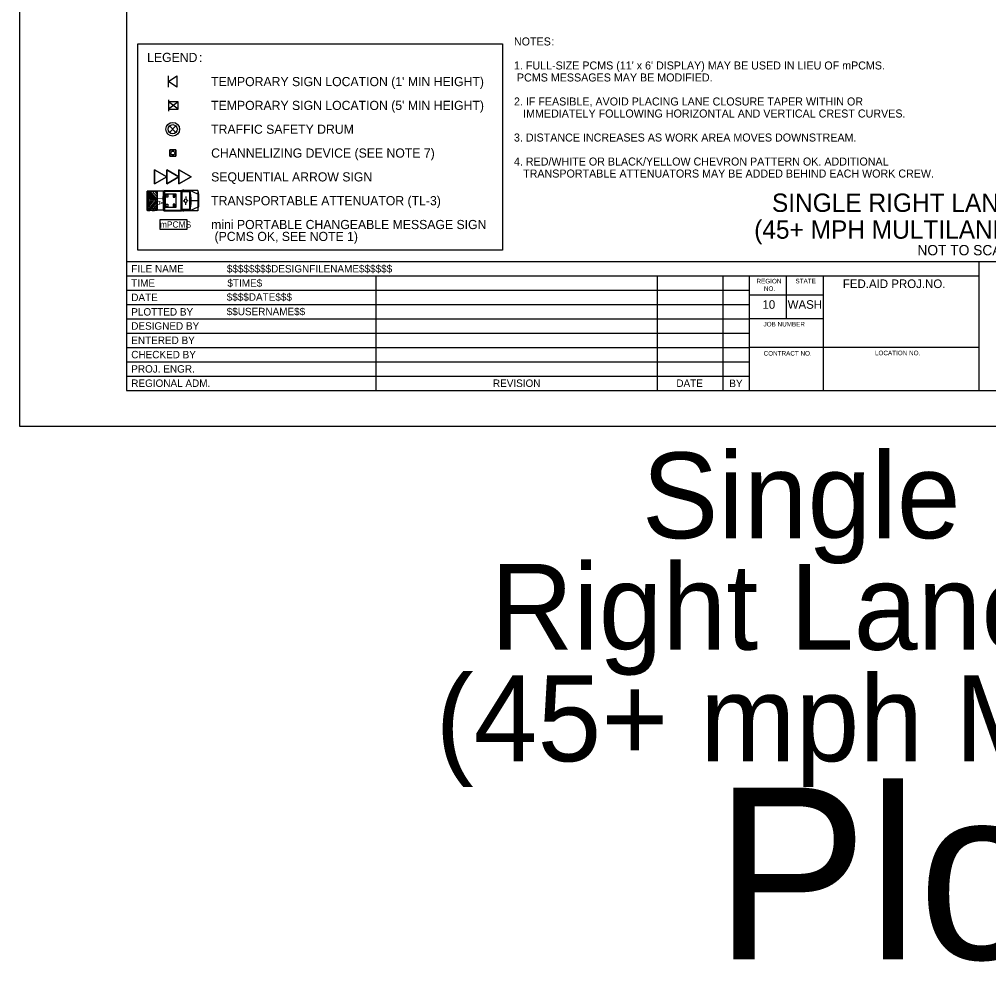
# Model space of a CAD drawing. Extents: x 99958 to 100176, y 99935 to 100011.
# Drawn here: x 99999.06 to 100007.54, y 99995.01 to 100003.24 of the extents above; entities that cross this region are included whole.
import ezdxf

# ---------------------------------------------------------------- set-up
doc = ezdxf.new("R2010")
doc.units = 0
for name, color, linetype in [('SH_DE_DetailHeading1Text', 7, 'Continuous'), ('SH_GI_GeneralNotesBodyText', 7, 'Continuous'), ('SH_GI_PlotLimits', 7, 'Continuous'), ('SH_GI_SheetBorder', 7, 'Continuous'), ('SH_GI_SheetLocationText', 7, 'Continuous'), ('SH_GI_SheetTextInCells', 7, 'Continuous'), ('SH_GI_TitleBlockText', 7, 'Continuous'), ('TR_WZ_PCMS', 7, 'Continuous'), ('TR_WZ_PortableSignMount5ftMinBlk-Wht', 7, 'Continuous'), ('TR_WZ_PortableSignMountBlk-Wht', 7, 'Continuous'), ('TR_WZ_SequentialArrowSign', 7, 'Continuous'), ('TR_WZ_TrafficCone', 7, 'Continuous'), ('TR_WZ_TrafficSafetyDrum', 7, 'Continuous'), ('TR_WZ_TransportableAttenuator', 7, 'Continuous'), ('TR_WZ_WorkZoneTextCurrent', 7, 'Continuous')]:
    doc.layers.add(name, color=color, linetype=linetype)

msp = doc.modelspace()

# ---------------------------------------------------------------- linework, layer by layer
at = {"layer": 'SH_GI_PlotLimits'}
msp.add_lwpolyline([(99999.0625, 99999.6875), (100016.0625, 99999.6875), (100016.0625, 100010.6875), (99999.0625, 100010.6875)], close=True, dxfattribs=at)
at = {"layer": 'SH_GI_SheetBorder'}
for p, q in [((100000, 100010.375), (100000, 100000)), ((100000, 100001.1259), (100015.75, 100001.1259)), ((100007.4566, 100000), (100007.4566, 100001.1259)), ((100000, 100001.0008), (100007.4566, 100001.0008)), ((100002.179, 100001.0008), (100002.179, 100000)), ((100004.641, 100001.0008), (100004.641, 100000)), ((100005.2164, 100001.0008), (100005.2164, 100000)), ((100005.4451, 100001.0008), (100005.4451, 100000)), ((100005.7719, 100000.6255), (100005.7719, 100001.0008)), ((100006.0956, 100000), (100006.0956, 100001.0008)), ((100000, 100000.8757), (100002.1821, 100000.8757)), ((100002.1821, 100000.8757), (100005.4466, 100000.8757)), ((100006.0958, 100000.831), (100005.4466, 100000.831)), ((100000, 100000.7506), (100002.1821, 100000.7506)), ((100002.1821, 100000.7506), (100005.4466, 100000.7506)), ((100000, 100000.6255), (100005.4466, 100000.6255)), ((100006.0958, 100000.6255), (100005.4466, 100000.6255)), ((100000, 100000.5004), (100005.4466, 100000.5004)), ((100000, 100000.3753), (100005.4466, 100000.3753)), ((100007.4566, 100000.3753), (100005.4466, 100000.3753)), ((100000, 100000.2502), (100005.4466, 100000.2502)), ((100000, 100000.1251), (100005.4466, 100000.1251)), ((100000, 100000), (100015.75, 100000))]:
    msp.add_line(p, q, dxfattribs=at)
at = {"layer": 'TR_WZ_PCMS'}
msp.add_lwpolyline([(100000.2899, 100001.41), (100000.5299, 100001.41), (100000.5299, 100001.49), (100000.2899, 100001.49)], close=True, dxfattribs=at)
msp.add_lwpolyline([(100000.2899, 100001.41), (100000.5299, 100001.41), (100000.5299, 100001.49), (100000.2899, 100001.49), (100000.2899, 100001.41)], dxfattribs=at)
at = {"layer": 'TR_WZ_PortableSignMount5ftMinBlk-Wht'}
for p, q in [((100000.3682, 100002.5414), (100000.3682, 100002.4414)), ((100000.4516, 100002.4589), (100000.3682, 100002.5239)), ((100000.4516, 100002.5239), (100000.3682, 100002.4589)), ((100000.4099, 100002.4914), (100000.4099, 100002.4914)), ((100000.41, 100002.4914), (100000.41, 100002.4914))]:
    msp.add_line(p, q, dxfattribs=at)
msp.add_lwpolyline([(100000.4516, 100002.4589), (100000.4516, 100002.5239), (100000.3682, 100002.5239), (100000.3682, 100002.4589)], close=True, dxfattribs=at)
at = {"layer": 'TR_WZ_PortableSignMountBlk-Wht'}
msp.add_line((100000.3682, 100002.6497), (100000.3682, 100002.7497), dxfattribs=at)
msp.add_lwpolyline([(100000.3682, 100002.6996), (100000.44, 100002.7497), (100000.44, 100002.6497)], close=True, dxfattribs=at)
at = {"layer": 'TR_WZ_SequentialArrowSign'}
for points in [[(100000.3508, 100001.8666), (100000.2441, 100001.8048), (100000.2441, 100001.9284), (100000.3508, 100001.8666)], [(100000.2441, 100001.9284), (100000.2441, 100001.8048), (100000.3508, 100001.8666), (100000.2441, 100001.9284)], [(100000.4575, 100001.8666), (100000.3508, 100001.8048), (100000.3508, 100001.8666), (100000.3508, 100001.9284), (100000.4575, 100001.8666)], [(100000.3508, 100001.9284), (100000.3508, 100001.8666), (100000.3508, 100001.8048), (100000.4575, 100001.8666), (100000.3508, 100001.9284)], [(100000.5641, 100001.8666), (100000.4575, 100001.8048), (100000.4575, 100001.8666), (100000.4575, 100001.9284), (100000.5641, 100001.8666)], [(100000.4575, 100001.9284), (100000.4575, 100001.8666), (100000.4575, 100001.8048), (100000.5641, 100001.8666), (100000.4575, 100001.9284)]]:
    msp.add_lwpolyline(points, dxfattribs=at)
at = {"layer": 'TR_WZ_TrafficCone'}
for points in [[(100000.4308, 100002.1016), (100000.4308, 100002.0482), (100000.3775, 100002.0482), (100000.3775, 100002.1016), (100000.4308, 100002.1016)], [(100000.3775, 100002.1016), (100000.3775, 100002.0482), (100000.4308, 100002.0482), (100000.4308, 100002.1016), (100000.3775, 100002.1016)]]:
    msp.add_lwpolyline(points, dxfattribs=at)
msp.add_circle((100000.4041, 100002.0749), 0.0167, dxfattribs=at)
at = {"layer": 'TR_WZ_TrafficSafetyDrum'}
for p, q in [((100000.4324, 100002.3114), (100000.3758, 100002.2549)), ((100000.4324, 100002.2549), (100000.3758, 100002.3114))]:
    msp.add_line(p, q, dxfattribs=at)
for radius in [0.06, 0.06, 0.04]:
    msp.add_circle((100000.4041, 100002.2832), radius, dxfattribs=at)
at = {"layer": 'TR_WZ_TransportableAttenuator'}
for p, q in [((100000.1791, 100001.7269), (100000.2355, 100001.659)), ((100000.1791, 100001.705), (100000.1791, 100001.7269)), ((100000.2355, 100001.659), (100000.1791, 100001.7269)), ((100000.1791, 100001.7269), (100000.1791, 100001.705)), ((100000.2174, 100001.6592), (100000.1791, 100001.705)), ((100000.1791, 100001.705), (100000.2174, 100001.6592)), ((100000.2551, 100001.6585), (100000.185, 100001.743)), ((100000.185, 100001.743), (100000.2041, 100001.743)), ((100000.185, 100001.743), (100000.2551, 100001.6585)), ((100000.2041, 100001.743), (100000.185, 100001.743)), ((100000.2041, 100001.743), (100000.2676, 100001.6659)), ((100000.2676, 100001.6659), (100000.2041, 100001.743)), ((100000.2676, 100001.6908), (100000.2248, 100001.743)), ((100000.2248, 100001.743), (100000.2439, 100001.743)), ((100000.2439, 100001.743), (100000.2248, 100001.743)), ((100000.2248, 100001.743), (100000.2676, 100001.6908)), ((100000.2439, 100001.743), (100000.2676, 100001.7144)), ((100000.2676, 100001.7144), (100000.2439, 100001.743)), ((100000.2676, 100001.574), (100000.2676, 100001.743)), ((100000.3279, 100001.743), (100000.2676, 100001.743)), ((100000.2676, 100001.7144), (100000.2676, 100001.6908)), ((100000.2676, 100001.6908), (100000.2676, 100001.7144)), ((100000.3208, 100001.7399), (100000.3208, 100001.5768)), ((100000.3241, 100001.7454), (100000.3274, 100001.7454)), ((100000.3274, 100001.7454), (100000.3274, 100001.5713)), ((100000.3279, 100001.7483), (100000.4803, 100001.7483)), ((100000.3279, 100001.7483), (100000.3279, 100001.5683)), ((100000.3279, 100001.7427), (100000.3279, 100001.574)), ((100000.3323, 100001.7411), (100000.3323, 100001.5755)), ((100000.3323, 100001.7411), (100000.476, 100001.7411)), ((100000.476, 100001.7411), (100000.476, 100001.5755)), ((100000.4803, 100001.7483), (100000.4803, 100001.5683)), ((100000.4824, 100001.7483), (100000.4824, 100001.5683)), ((100000.6223, 100001.7483), (100000.4824, 100001.7483)), ((100000.551, 100001.7344), (100000.4824, 100001.7344)), ((100000.5014, 100001.7509), (100000.493, 100001.7509)), ((100000.5175, 100001.694), (100000.5175, 100001.6794)), ((100000.551, 100001.7483), (100000.5421, 100001.7344)), ((100000.551, 100001.7483), (100000.551, 100001.5683)), ((100000.5523, 100001.7483), (100000.5523, 100001.5683)), ((100000.6223, 100001.7153), (100000.5523, 100001.7483)), ((100000.6223, 100001.7483), (100000.6223, 100001.5683)), ((100000.6223, 100001.7483), (100000.6291, 100001.712)), ((100000.6291, 100001.712), (100000.6291, 100001.6047)), ((100000.1791, 100001.6818), (100000.1987, 100001.6586)), ((100000.1791, 100001.635), (100000.1791, 100001.6818)), ((100000.1987, 100001.6586), (100000.1791, 100001.6818)), ((100000.1791, 100001.6818), (100000.1791, 100001.635)), ((100000.1791, 100001.6131), (100000.2174, 100001.6592)), ((100000.2174, 100001.6592), (100000.1791, 100001.6131)), ((100000.2355, 100001.659), (100000.1791, 100001.5911)), ((100000.1791, 100001.5911), (100000.2355, 100001.659)), ((100000.1987, 100001.6586), (100000.1791, 100001.635)), ((100000.1791, 100001.635), (100000.1987, 100001.6586)), ((100000.1791, 100001.5911), (100000.1791, 100001.6131)), ((100000.1791, 100001.6131), (100000.1791, 100001.5911)), ((100000.1849, 100001.5739), (100000.2551, 100001.6585)), ((100000.2551, 100001.6585), (100000.1849, 100001.5739)), ((100000.2676, 100001.6509), (100000.2037, 100001.5739)), ((100000.2037, 100001.5739), (100000.2676, 100001.6509)), ((100000.2243, 100001.5739), (100000.2676, 100001.626)), ((100000.2676, 100001.626), (100000.2243, 100001.5739)), ((100000.2676, 100001.6659), (100000.2676, 100001.6509)), ((100000.2676, 100001.6509), (100000.2676, 100001.6659)), ((100000.2676, 100001.626), (100000.2676, 100001.6011)), ((100000.2676, 100001.6011), (100000.2676, 100001.626)), ((100000.3208, 100001.671), (100000.3274, 100001.6676)), ((100000.3208, 100001.6456), (100000.3274, 100001.649)), ((100000.3226, 100001.6583), (100000.3257, 100001.6583)), ((100000.3241, 100001.6608), (100000.3241, 100001.6558)), ((100000.4951, 100001.6584), (100000.5045, 100001.6584)), ((100000.507, 100001.658), (100000.507, 100001.658)), ((100000.5175, 100001.6226), (100000.5175, 100001.6372)), ((100000.5398, 100001.6584), (100000.5305, 100001.6584)), ((100000.6223, 100001.6583), (100000.566, 100001.6583)), ((100000.2037, 100001.5739), (100000.1849, 100001.5739)), ((100000.1849, 100001.5739), (100000.2037, 100001.5739)), ((100000.2446, 100001.5739), (100000.2243, 100001.5739)), ((100000.2243, 100001.5739), (100000.2446, 100001.5739)), ((100000.2676, 100001.6011), (100000.2446, 100001.5739)), ((100000.2446, 100001.5739), (100000.2676, 100001.6011)), ((100000.3279, 100001.574), (100000.2676, 100001.574)), ((100000.3241, 100001.5713), (100000.3274, 100001.5713)), ((100000.3279, 100001.5683), (100000.4803, 100001.5683)), ((100000.3323, 100001.5755), (100000.476, 100001.5755)), ((100000.551, 100001.5823), (100000.4824, 100001.5823)), ((100000.6223, 100001.5683), (100000.4824, 100001.5683)), ((100000.5014, 100001.5658), (100000.493, 100001.5658)), ((100000.5437, 100001.5823), (100000.551, 100001.5683)), ((100000.6223, 100001.6013), (100000.5523, 100001.5683)), ((100000.6223, 100001.5683), (100000.6291, 100001.6047))]:
    msp.add_line(p, q, dxfattribs=at)
for points in [[(100000.2676, 100001.5739), (100000.1791, 100001.5739), (100000.1791, 100001.743), (100000.2676, 100001.743)], [(100000.3398, 100001.7183), (100000.4298, 100001.7183), (100000.4298, 100001.5983), (100000.3398, 100001.5983)], [(100000.3473, 100001.7108), (100000.3623, 100001.7108), (100000.3623, 100001.6883), (100000.3473, 100001.6883)], [(100000.4223, 100001.7108), (100000.4073, 100001.7108), (100000.4073, 100001.6883), (100000.4223, 100001.6883)], [(100000.3473, 100001.6283), (100000.3623, 100001.6283), (100000.3623, 100001.6058), (100000.3473, 100001.6058)], [(100000.4223, 100001.6283), (100000.4073, 100001.6283), (100000.4073, 100001.6058), (100000.4223, 100001.6058)]]:
    msp.add_lwpolyline(points, close=True, dxfattribs=at)
msp.add_lwpolyline([(100000.2676, 100001.743), (100000.1791, 100001.743), (100000.1791, 100001.5739), (100000.2676, 100001.574)], dxfattribs=at)
for centre, major_axis, start_param, end_param in [((100000.3241, 100001.7399), (0, 0.00549), 6.283185, 7.853982), ((100000.4523, 100001.6583), (0, 0.1889), 4.215852, 5.209111), ((100000.3241, 100001.5768), (0, -0.00549), 4.712389, 6.283185)]:
    msp.add_ellipse(centre, major_axis=major_axis, ratio=0.60201, start_param=start_param, end_param=end_param, dxfattribs=at)
for centre, major_axis in [((100000.3241, 100001.6583), (0, -0.00254)), ((100000.5175, 100001.6583), (0, -0.0173))]:
    msp.add_ellipse(centre, major_axis=major_axis, ratio=0.60201, dxfattribs=at)
at = {"layer": 'TR_WZ_WorkZoneTextCurrent'}
msp.add_lwpolyline([(100000.1, 100003.031), (100003.2886, 100003.031), (100003.2886, 100001.2259), (100000.1, 100001.2259)], close=True, dxfattribs=at)

# ---------------------------------------------------------------- texts
at = {"layer": 'SH_DE_DetailHeading1Text'}
for s, height, p in [('SINGLE RIGHT LANE CLOSURE', 0.16, (100005.6453, 100001.5606)), ('(45+ MPH MULTILANE HIGHWAYS)', 0.16, (100005.4898, 100001.3259)), ('NOT TO SCALE', 0.09, (100006.9175, 100001.1809))]:
    msp.add_text(s, height=height, rotation=360, dxfattribs=at).set_placement(p)
at = {"layer": 'SH_GI_GeneralNotesBodyText'}
for s, p in [('NOTES', (100003.3886, 100003.0156)), (':', (100003.7161, 100003.0156)), ("1. FULL-SIZE PCMS (11' x 6' DISPLAY) MAY BE USED IN LIEU OF mPCMS.", (100003.3886, 100002.8056)), (' PCMS MESSAGES MAY BE MODIFIED.', (100003.3886, 100002.7006)), ('2. IF FEASIBLE, AVOID PLACING LANE CLOSURE TAPER WITHIN OR ', (100003.3886, 100002.4906)), ('IMMEDIATELY FOLLOWING HORIZONTAL AND VERTICAL CREST CURVES.', (100003.4686, 100002.3856)), ('3. DISTANCE INCREASES AS WORK AREA MOVES DOWNSTREAM.', (100003.3886, 100002.1756)), ('4. RED/WHITE OR BLACK/YELLOW CHEVRON PATTERN OK. ADDITIONAL ', (100003.3886, 100001.9656)), ('TRANSPORTABLE ATTENUATORS MAY BE ADDED BEHIND EACH WORK CREW.', (100003.4686, 100001.8606))]:
    msp.add_text(s, height=0.07, rotation=360, dxfattribs=at).set_placement(p)
at = {"layer": 'SH_GI_SheetLocationText'}
for s, height, p in [('Single PCMS', 0.75, (100004.5076, 99998.7071)), ('Right Lane Closure', 0.75, (100003.1834, 99997.7321)), ('(45+ mph ML Hwys)', 0.75, (100002.7028, 99996.7571)), ('Plot 1', 1.5, (100005.1422, 99995.0267))]:
    msp.add_text(s, height=height, dxfattribs=at).set_placement(p)
at = {"layer": 'SH_GI_SheetTextInCells'}
for s, height, p in [('FILE NAME', 0.06505, (100000.041, 100001.0308)), ('TIME', 0.06505, (100000.041, 100000.9057)), ('REGION', 0.04003, (100005.5099, 100000.9352)), ('STATE', 0.04003, (100005.8511, 100000.9357)), ('FED.AID PROJ.NO.', 0.07506, (100006.2652, 100000.8945)), ('DATE', 0.06505, (100000.041, 100000.7806)), ('NO.', 0.04003, (100005.5752, 100000.869)), ('10', 0.07506, (100005.5621, 100000.7131)), ('WASH', 0.07506, (100005.7826, 100000.7131)), ('PLOTTED BY', 0.06505, (100000.041, 100000.6538)), ('DESIGNED BY', 0.065052, (100000.041, 100000.5304)), ('JOB NUMBER', 0.04003, (100005.5712, 100000.5587)), ('ENTERED BY', 0.06505, (100000.041, 100000.4053)), ('CHECKED BY', 0.06505, (100000.041, 100000.2802)), ('CONTRACT NO.', 0.040032, (100005.5725, 100000.3037)), ('LOCATION NO.', 0.040032, (100006.5465, 100000.3067)), ('PROJ. ENGR.', 0.065052, (100000.041, 100000.1551)), ('REGIONAL ADM.', 0.065052, (100000.041, 100000.03)), ('REVISION', 0.06505, (100003.2048, 100000.03)), ('DATE', 0.06505, (100004.8091, 100000.03)), ('BY', 0.06505, (100005.2725, 100000.0285))]:
    msp.add_text(s, height=height, dxfattribs=at).set_placement(p)
at = {"layer": 'SH_GI_TitleBlockText'}
for s, height, p in [('$$$$$$$$DESIGNFILENAME$$$$$$', 0.065052, (100000.8775, 100001.0308)), ('$TIME$', 0.06505, (100000.882, 100000.9059)), ('$$$$DATE$$$', 0.065052, (100000.8759, 100000.7835)), ('$$USERNAME$$', 0.065052, (100000.8759, 100000.6567))]:
    msp.add_text(s, height=height, dxfattribs=at).set_placement(p)
at = {"layer": 'TR_WZ_PCMS'}
msp.add_text('mPCMS', height=0.055, rotation=360, dxfattribs=at).set_placement((100000.2914, 100001.4225))
at = {"layer": 'TR_WZ_TransportableAttenuator'}
msp.add_text('TA', height=0.045, rotation=269.99999, dxfattribs=at).set_placement((100000.2717, 100001.6978))
at = {"layer": 'TR_WZ_WorkZoneTextCurrent'}
for s, p in [('LEGEND', (100000.18, 100002.871)), (':', (100000.6328, 100002.871)), ("TEMPORARY SIGN LOCATION (1' MIN HEIGHT)", (100000.74, 100002.6597)), ("TEMPORARY SIGN LOCATION (5' MIN HEIGHT)", (100000.74, 100002.4514)), ('TRAFFIC SAFETY DRUM', (100000.74, 100002.2432)), ('CHANNELIZING DEVICE (SEE NOTE 7)', (100000.74, 100002.0349)), ('SEQUENTIAL ARROW SIGN', (100000.74, 100001.8266)), ('TRANSPORTABLE ATTENUATOR (TL-3)', (100000.74, 100001.6183)), ('mini PORTABLE CHANGEABLE MESSAGE SIGN', (100000.74, 100001.41)), (' (PCMS OK, SEE NOTE 1)', (100000.74, 100001.3059))]:
    msp.add_text(s, height=0.08, rotation=360, dxfattribs=at).set_placement(p)

doc.saveas('drawing.dxf')
